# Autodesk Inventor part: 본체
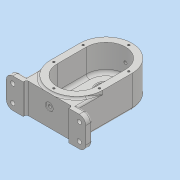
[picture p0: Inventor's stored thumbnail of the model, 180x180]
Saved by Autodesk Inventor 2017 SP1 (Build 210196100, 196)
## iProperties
Part Number: 본체
Material: 일반
Document SubType Name: Modeling
Designer: MRC
Density: 1 g/cm^3
Appearance: 기본값
Author: MRC
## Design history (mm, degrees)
sketch "스케치1"
  geometry: L1 (0, 0)-(0, -45); L2 (-40, 0)-(-40, -45); L3 (40, -45)-(40, 0); A1 r 40 centre (0, 0) between (40, 0) and (-40, 0); A2 r 40 centre (0, -45) between (-40, -45) and (40, -45); 1 further point
  constraints: 8 end point, 4 point on circle, 4 tangent, 2 centre point, 1 midpoint, 1 parallel, 1 vertical
  dimensions: "d0" = 45 distance of L1.start L1.end; "d1" = 80 diameter of A2
extrude "돌출1" new body sketch "스케치1" distance "d2" = 21; taper "d4" = 0 deg; dims "d3" = 28, "d5" = 0
sketch "스케치2"
  geometry: L1 (-40, 0)-(-40, -45) reference; L2 (40, -45)-(40, 0) reference; L3 (-30, 0)-(-30, -45); L4 (30, -45)-(30, 0); A1 r 40 centre (0, -45) between (-40, -45) and (40, -45) reference; A2 r 40 centre (0, 0) between (40, 0) and (-40, 0) reference; A3 r 30 centre (0, -45) between (-30, -45) and (30, -45); A4 r 30 centre (0, 0) between (30, 0) and (-30, 0)
  constraints: 4 end point, 4 point on circle, 2 centre point, 3 other
  dimensions: "d6" = 10 radial gap between concentric circles of A2 A4
extrude "돌출2" cut sketch "스케치2" distance "d7" = 41; taper "d8" = 0 deg
sketch "스케치3"
  geometry: L1 (0, 0)-(0, -45); L2 (-26, 0)-(-26, -45); L3 (26, -45)-(26, 0); A1 r 40 centre (0, 0) between (40, 0) and (-40, 0) reference; A2 r 40 centre (0, -45) between (-40, -45) and (40, -45) reference; A3 r 26 centre (0, 0) between (26, 0) and (-26, 0); A4 r 26 centre (0, -45) between (-26, -45) and (26, -45); 1 further point
  constraints: 8 end point, 4 point on circle, 4 tangent, 2 centre point, 1 midpoint, 1 parallel, 1 vertical
  dimensions: "d9" = 52 diameter of A4
extrude "돌출3" join sketch "스케치3" distance "d10" = 11; taper "d11" = 0 deg
sketch "스케치4"
  geometry: L1 (-26, 0)-(-26, -45) reference; L2 (26, -45)-(26, 0) reference; L3 (-26, -30)-(26, -30); A1 r 26 centre (0, 0) between (26, 0) and (-26, 0) reference
  constraints: 2 end point, 2 point on line, 1 perpendicular
  dimensions: "d12" = 30 distance from line of A1.centre L3
extrude "돌출4" cut sketch "스케치4" distance "d13" = 3; taper "d14" = 0 deg
sketch "스케치5"
  geometry: A1 r 30 centre (0, 0) between (30, 0) and (-30, 0) reference
hole "구멍1" sketch "스케치5" at (0, 0) diameter "d15" = 22; stored, may be unused: countersink angle "d19" = 90 deg, drill point angle "d21" = 118 deg; dims "d16" = 6, "d17" = 28, "d18" = 8, "d20" = 8
sketch "스케치6"
  geometry: A1 r 30 centre (0, -45) between (-30, -45) and (30, -45) reference
hole "구멍2" sketch "스케치6" at (0, -45) diameter "d22" = 20; stored, may be unused: countersink angle "d26" = 90 deg, drill point angle "d28" = 0 deg; dims "d23" = 6, "d24" = 28, "d25" = 8, "d27" = 12
sketch "스케치7"
  geometry: C1 r 11 at (0, 0) reference
hole "구멍3" sketch "스케치7" at (0, 0) diameter "d29" = 28; stored, may be unused: countersink angle "d33" = 90 deg, drill point angle "d35" = 0 deg; dims "d30" = 6, "d31" = 28, "d32" = 8, "d34" = 4
sketch "스케치8"
  geometry: A1 r 30 centre (0, -45) between (-30, -45) and (30, -45) reference; 1 further point
  constraints: 1 horizontal alignment
  dimensions: "d36" = 35 distance of point (-35, -45) A1.centre
hole "구멍4" sketch "스케치8" at (-35, -45) diameter "d37" = 3.242; stored, may be unused: countersink angle "d41" = 90 deg, drill point angle "d43" = 118 deg; dims "d38" = 8, "d39" = 28, "d40" = 8, "d42" = 10
sketch "스케치9"
  geometry: A1 r 30 centre (0, 0) between (30, 0) and (-30, 0) reference; 1 further point
  constraints: 1 horizontal alignment
  dimensions: "d47" = 35 distance of point (-35, 0) A1.centre
hole "구멍5" sketch "스케치9" at (-35, 0) diameter "d48" = 3.242; stored, may be unused: countersink angle "d52" = 90 deg, drill point angle "d54" = 118 deg; dims "d49" = 8, "d50" = 28, "d51" = 8, "d53" = 10
node "작업 평면1"
sketch "스케치10"
  geometry: L1 (61, -28)-(-61, -28); L2 (-61, -28)-(-61, 18); L3 (-61, 18)-(61, 18); L4 (61, 18)-(61, -28); L5 (61, -28)-(-61, 18); L6 (-61, -28)-(61, 18); L7 (-26, -39)-(26, -39) reference; 3 further points
  constraints: 12 end point, 3 midpoint, 2 parallel, 1 horizontal, 1 perpendicular, 1 vertical alignment
  dimensions: "d59" = 122 distance of L2.end L3.end; "d60" = 46 distance of L1.end L2.end; "d61" = 11 distance between parallel lines of L7 L1
extrude "돌출5" join sketch "스케치10" distance "d62" = 10; taper "d63" = 0 deg
sketch "스케치11"
  geometry: L1 (21, 28.89)-(21, 13.881); L2 (21, 92)-(21, 47) reference; 1 further point
  constraints: 2 end point, 1 collinear, 1 vertical
feature "리브1" sketch "스케치11" dims "d64" = 1, "d65" = 46, "d66" = 0, "d67" = 0, "d68" = 1, "d69" = 1
node "작업 평면2"
sketch "스케치12"
  geometry: C1 r 6 at (0, 0); 1 further point
  constraints: 1 centre point, 1 coincident
  dimensions: "d71" = 12 diameter of C1
extrude "돌출6" join sketch "스케치12" stored distance "d72" = 10; taper "d73" = 0 deg
sketch "스케치13"
  geometry: C1 r 6 at (0, 0) reference
hole "구멍6" sketch "스케치13" at (0, 0) diameter "d74" = 4.917; stored, may be unused: countersink angle "d78" = 90 deg, drill point angle "d80" = 118 deg; dims "d75" = 12, "d76" = 28, "d77" = 8, "d79" = 17.1
sketch "스케치14"
  geometry: L1 (61, 18)-(-61, 18) reference; L2 (-61, -28)-(61, -28) reference; L3 (35, 18)-(-35, 18); L4 (-35, 18)-(-35, -28); L5 (-35, -28)-(35, -28); L6 (35, -28)-(35, 18); 1 further point
  constraints: 8 end point, 2 collinear, 2 parallel, 1 horizontal, 1 perpendicular
  dimensions: "d81" = 70 distance between parallel lines of L4 L6; "d82" = 35 distance from line of L4 point (0, 0) (= 0.5 x d81)
extrude "돌출7" cut sketch "스케치14" distance "d83" = 5; taper "d84" = 0 deg
sketch "스케치15"
  geometry: 1 further point
hole "구멍7" sketch "스케치15" at (0, 0) diameter "d85" = 4.917; stored, may be unused: countersink angle "d89" = 90 deg, drill point angle "d91" = 118 deg; dims "d86" = 12, "d87" = 12, "d88" = 1, "d90" = 17.1
fillet "모깎기1" dims "d92" = 10
sketch "스케치16"
  geometry: L1 (-61, 18)-(-61, -8) reference; L2 (-51, -18)-(-40, -18) reference; L3 (-40, -18)-(-40, 28) reference; L4 (-40, 28)-(-51, 28) reference; A1 r 10 centre (51, 18) between (61, 18) and (51, 28) reference; A2 r 10 centre (51, -8) between (51, -18) and (61, -8) reference; A3 r 10 centre (-51, 18) between (-51, 28) and (-61, 18) reference; A4 r 10 centre (-51, -8) between (-61, -8) and (-51, -18) reference; 1 further point
hole "구멍8" sketch "스케치16" at (-51, 18), (-51, -8), (51, 18), (51, -8) diameter "d93" = 6.6; stored, may be unused: countersink angle "d97" = 90 deg, drill point angle "d99" = 118 deg; dims "d94" = 12, "d95" = 11, "d96" = 2, "d98" = 17.1
fillet "모깎기2" dims "d100" = 3
chamfer "모따기1" distance "d101" = 1; stored, may be unused: second distance "d102" = 2, angle "d103" = 45 deg
fillet "모깎기3" dims "d104" = 3, "d105" = 0.3
fillet "모깎기4" dims "d106" = 3
sketch "스케치17"
  geometry: A1 r 26 centre (0, 0) between (26, 0) and (-26, 0) reference; 1 further point
  constraints: 1 vertical alignment
  dimensions: "d107" = 20 distance of A1.centre point (0, 20)
hole "구멍9" sketch "스케치17" at (0, 20) diameter "d108" = 3.242; stored, may be unused: countersink angle "d112" = 90 deg, drill point angle "d114" = 118 deg; dims "d109" = 8, "d110" = 11, "d111" = 2, "d113" = 10
sketch "스케치18"
  geometry: L1 (-35, -92)-(-51, -92) reference; A1 r 29 centre (0, 0) between (29, 0) and (-29, 0) reference; 1 further point
  constraints: 1 vertical alignment, 1 other
  dimensions: "d118" = 12 distance from line of L1 point (0, -80)
feature "엠보싱1" sketch "스케치18" dims "d0" = 45, "d1" = 80, "d119" = 0.5, "d120" = 0
fillet "모깎기5" dims "d121" = 5
node "솔리드1"
pattern_circular "원형 패턴1" dims angle "d45" = 180 deg
pattern_circular "원형 패턴2" dims angle "d56" = 180 deg
mirror "미러1"
pattern_circular "원형 패턴3" dims angle "d116" = 360 deg
node "투영된 루프1"
other parameters: "d58" = -92, "d70" = 43
